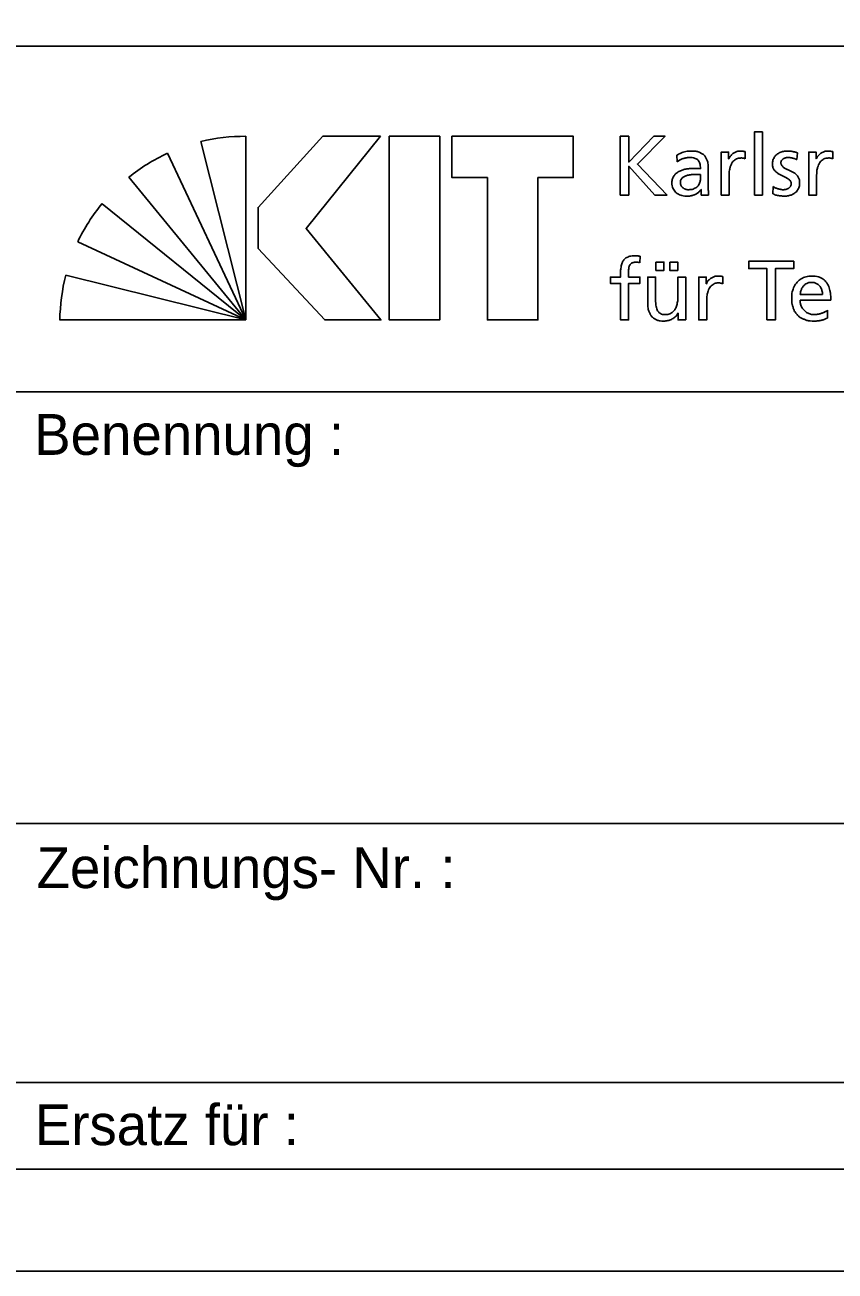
# Model space of a CAD drawing. Extents: x 0 to 148, y 0 to 105.
# Drawn here: x 126.41 to 136.33, y 0 to 15.26 of the extents above; entities that cross this region are included whole.
import ezdxf

# ---------------------------------------------------------------- set-up
doc = ezdxf.new("R2010")
doc.units = 0
doc.layers.add('90_Plankopf', color=7, linetype='Continuous')

msp = doc.modelspace()

# ---------------------------------------------------------------- linework, layer by layer
at = {"layer": '90_Plankopf'}
for p, q in [((102.78, 14.998), (147.25, 14.998)), ((102.78, 14.998), (147.25, 14.998)), ((129.12, 11.647), (129.12, 13.896)), ((133.702, 13.897), (133.702, 13.176)), ((128.569, 13.833), (129.12, 11.647)), ((129.12, 11.647), (128.158, 13.688)), ((134.395, 13.665), (134.4, 13.583)), ((135.232, 13.621), (135.232, 13.708)), ((135.864, 13.61), (135.872, 13.694)), ((136.303, 13.621), (136.303, 13.708)), ((134.78, 13.28), (134.78, 13.497)), ((127.686, 13.396), (129.12, 11.647)), ((134.683, 13.427), (134.683, 13.381)), ((135.574, 13.28), (135.569, 13.193)), ((133.702, 13.176), (133.806, 13.176)), ((134.126, 13.176), (134.277, 13.176)), ((129.12, 11.647), (127.358, 13.071)), ((127.06, 12.603), (129.12, 11.647)), ((133.943, 12.348), (133.947, 12.427)), ((129.12, 11.647), (126.914, 12.197)), ((134.957, 12.091), (134.957, 12.178)), ((136.177, 11.96), (135.904, 11.96)), ((135.904, 11.888), (136.28, 11.888)), ((136.239, 11.668), (136.239, 11.765)), ((126.841, 11.647), (129.12, 11.647)), ((126.25, 10.768), (147.25, 10.768)), ((126.25, 5.48), (147.25, 5.48)), ((126.25, 2.308), (147.25, 2.308)), ((147.25, 1.25), (102.78, 1.25)), ((105.7, 1.25), (147.25, 1.25)), ((105.7, 1.25), (147.25, 1.25))]:
    msp.add_line(p, q, dxfattribs=at)
for points in [[(0, 0), (148.5, 0), (148.5, 105), (0, 105)], [(6.25, 103.75), (147.25, 103.75), (147.25, 1.25), (6.25, 1.25)], [(130.767, 13.897), (130.059, 13.897), (129.268, 13.025), (129.268, 12.523), (130.084, 11.647), (130.771, 11.647), (129.856, 12.766)], [(131.493, 13.897), (131.493, 11.647), (130.875, 11.647), (130.875, 13.897)], [(131.641, 13.897), (131.641, 13.39), (132.075, 13.39), (132.075, 11.647), (132.693, 11.647), (132.693, 13.39), (133.127, 13.39), (133.127, 13.897)]]:
    msp.add_lwpolyline(points, close=True, dxfattribs=at)
for points in [[(134.277, 13.176), (133.912, 13.556), (134.25, 13.897), (134.113, 13.897), (133.806, 13.58), (133.806, 13.897), (133.702, 13.897)], [(135.345, 13.176), (135.442, 13.176), (135.442, 13.95), (135.345, 13.95), (135.345, 13.176)], [(135.03, 13.621), (135.028, 13.621), (135.028, 13.703), (134.938, 13.703), (134.938, 13.176), (135.035, 13.176), (135.035, 13.416)], [(136.102, 13.621), (136.1, 13.621), (136.1, 13.703), (136.009, 13.703), (136.009, 13.176), (136.106, 13.176), (136.106, 13.416)], [(133.806, 13.176), (133.806, 13.529), (134.126, 13.176)], [(134.691, 13.245), (134.693, 13.245), (134.693, 13.176), (134.784, 13.176)], [(135.498, 11.647), (135.601, 11.647), (135.601, 12.276), (135.825, 12.276), (135.825, 12.367), (135.274, 12.367), (135.274, 12.276), (135.498, 12.276), (135.498, 11.647)], [(133.706, 12.221), (133.706, 12.173), (133.582, 12.173), (133.582, 12.094), (133.706, 12.094), (133.706, 11.647), (133.803, 11.647), (133.803, 12.094), (133.942, 12.094), (133.942, 12.173), (133.803, 12.173), (133.803, 12.23)], [(134.139, 12.356), (134.139, 12.253), (134.236, 12.253), (134.236, 12.356), (134.139, 12.356)], [(134.308, 12.356), (134.308, 12.253), (134.405, 12.253), (134.405, 12.356), (134.308, 12.356)], [(134.135, 11.9), (134.135, 12.173), (134.038, 12.173), (134.038, 11.86)], [(134.504, 11.647), (134.504, 12.173), (134.407, 12.173), (134.407, 11.929)], [(134.756, 12.091), (134.754, 12.091), (134.754, 12.173), (134.663, 12.173), (134.663, 11.647), (134.76, 11.647), (134.76, 11.886)], [(134.408, 11.73), (134.41, 11.73), (134.41, 11.647), (134.504, 11.647)]]:
    msp.add_lwpolyline(points, dxfattribs=at)
for centre, start, end in [((129.112, 11.514), 89.8053, 103.1895), ((129.165, 11.529), 115.0126, 128.3968), ((129.204, 11.566), 140.7898, 154.174), ((129.223, 11.609), 165.7222, 179.1064)]:
    msp.add_arc(centre, 2.382, start, end, dxfattribs=at)
for points in [[(134.78, 13.497), (134.78, 13.545), (134.773, 13.585), (134.758, 13.617), (134.744, 13.65), (134.721, 13.674), (134.69, 13.69), (134.659, 13.707), (134.618, 13.715), (134.568, 13.715), (134.535, 13.715), (134.503, 13.71), (134.474, 13.701), (134.445, 13.692), (134.419, 13.68), (134.395, 13.665)], [(134.4, 13.583), (134.413, 13.594), (134.428, 13.604), (134.445, 13.611), (134.461, 13.62), (134.479, 13.626), (134.497, 13.63), (134.516, 13.634), (134.534, 13.637), (134.553, 13.637), (134.585, 13.637), (134.61, 13.631), (134.629, 13.621), (134.649, 13.611), (134.662, 13.596), (134.67, 13.575), (134.679, 13.555), (134.683, 13.53), (134.683, 13.499)], [(135.232, 13.708), (135.225, 13.709), (135.218, 13.71), (135.212, 13.712), (135.206, 13.713), (135.199, 13.713), (135.192, 13.714), (135.185, 13.715), (135.177, 13.715), (135.168, 13.715), (135.149, 13.715), (135.131, 13.711), (135.113, 13.703), (135.095, 13.695), (135.079, 13.684), (135.065, 13.67), (135.051, 13.656), (135.039, 13.639), (135.03, 13.621)], [(135.035, 13.416), (135.035, 13.46), (135.041, 13.498), (135.052, 13.53), (135.064, 13.562), (135.081, 13.587), (135.102, 13.604), (135.124, 13.621), (135.149, 13.63), (135.178, 13.63), (135.186, 13.631), (135.195, 13.63), (135.204, 13.629), (135.214, 13.627), (135.223, 13.625), (135.232, 13.621)], [(135.872, 13.694), (135.854, 13.7), (135.834, 13.705), (135.815, 13.709), (135.795, 13.713), (135.774, 13.715), (135.752, 13.715), (135.726, 13.715), (135.701, 13.712), (135.679, 13.705), (135.656, 13.698), (135.637, 13.688), (135.62, 13.675), (135.603, 13.662), (135.59, 13.645), (135.58, 13.625), (135.571, 13.604), (135.566, 13.58), (135.566, 13.553), (135.566, 13.532), (135.571, 13.514), (135.579, 13.498), (135.587, 13.483), (135.598, 13.47), (135.611, 13.459), (135.625, 13.447), (135.64, 13.437), (135.656, 13.429), (135.672, 13.42), (135.688, 13.412), (135.704, 13.404), (135.721, 13.397), (135.735, 13.389), (135.749, 13.38), (135.762, 13.373), (135.773, 13.363), (135.782, 13.353), (135.79, 13.343), (135.794, 13.331), (135.794, 13.318), (135.794, 13.304), (135.791, 13.292), (135.785, 13.282), (135.779, 13.272), (135.771, 13.265), (135.761, 13.259), (135.751, 13.253), (135.741, 13.249), (135.729, 13.246), (135.718, 13.244), (135.706, 13.242), (135.695, 13.242), (135.685, 13.242), (135.674, 13.244), (135.66, 13.247), (135.646, 13.249), (135.631, 13.253), (135.616, 13.259), (135.601, 13.265), (135.587, 13.271), (135.574, 13.28)], [(135.569, 13.193), (135.592, 13.181), (135.615, 13.174), (135.639, 13.17), (135.664, 13.166), (135.689, 13.164), (135.714, 13.164), (135.737, 13.164), (135.76, 13.167), (135.782, 13.174), (135.804, 13.18), (135.823, 13.191), (135.841, 13.204), (135.858, 13.217), (135.872, 13.234), (135.882, 13.255), (135.892, 13.276), (135.897, 13.3), (135.897, 13.328), (135.897, 13.352), (135.893, 13.372), (135.885, 13.389), (135.876, 13.406), (135.866, 13.42), (135.852, 13.431), (135.839, 13.443), (135.824, 13.453), (135.807, 13.461), (135.791, 13.469), (135.775, 13.477), (135.759, 13.484), (135.743, 13.491), (135.728, 13.499), (135.714, 13.507), (135.701, 13.515), (135.69, 13.524), (135.682, 13.534), (135.674, 13.545), (135.669, 13.557), (135.669, 13.573), (135.669, 13.587), (135.674, 13.599), (135.682, 13.609), (135.691, 13.618), (135.702, 13.625), (135.716, 13.63), (135.73, 13.634), (135.745, 13.637), (135.762, 13.637), (135.768, 13.637), (135.776, 13.636), (135.785, 13.634), (135.794, 13.633), (135.803, 13.631), (135.814, 13.628), (135.824, 13.626), (135.833, 13.623), (135.842, 13.62), (135.851, 13.616), (135.859, 13.613), (135.864, 13.61)], [(136.303, 13.708), (136.296, 13.709), (136.29, 13.71), (136.284, 13.712), (136.277, 13.713), (136.271, 13.713), (136.264, 13.714), (136.257, 13.715), (136.248, 13.715), (136.239, 13.715), (136.22, 13.715), (136.202, 13.711), (136.184, 13.703), (136.167, 13.695), (136.151, 13.684), (136.136, 13.67), (136.122, 13.656), (136.11, 13.639), (136.102, 13.621)], [(136.106, 13.416), (136.106, 13.46), (136.112, 13.498), (136.124, 13.53), (136.136, 13.562), (136.152, 13.587), (136.173, 13.604), (136.195, 13.621), (136.22, 13.63), (136.249, 13.63), (136.258, 13.631), (136.266, 13.63), (136.276, 13.629), (136.285, 13.627), (136.294, 13.625), (136.303, 13.621)], [(134.683, 13.499), (134.67, 13.5), (134.658, 13.501), (134.647, 13.501), (134.636, 13.501), (134.626, 13.501), (134.615, 13.501), (134.604, 13.501), (134.592, 13.501), (134.579, 13.501), (134.559, 13.501), (134.538, 13.5), (134.516, 13.496), (134.493, 13.492), (134.471, 13.487), (134.45, 13.478), (134.429, 13.47), (134.41, 13.46), (134.392, 13.446), (134.375, 13.433), (134.361, 13.416), (134.351, 13.397), (134.34, 13.377), (134.335, 13.354), (134.335, 13.328), (134.335, 13.29), (134.344, 13.259), (134.36, 13.235), (134.376, 13.211), (134.399, 13.193), (134.427, 13.181), (134.456, 13.17), (134.49, 13.164), (134.528, 13.164), (134.55, 13.164), (134.57, 13.167), (134.588, 13.172), (134.605, 13.177), (134.621, 13.184), (134.634, 13.192), (134.648, 13.2), (134.659, 13.209), (134.668, 13.218), (134.678, 13.228), (134.685, 13.236), (134.691, 13.245)], [(134.683, 13.381), (134.683, 13.354), (134.677, 13.331), (134.666, 13.31), (134.655, 13.289), (134.638, 13.273), (134.617, 13.261), (134.595, 13.249), (134.568, 13.243), (134.536, 13.242), (134.525, 13.242), (134.514, 13.244), (134.502, 13.248), (134.491, 13.252), (134.48, 13.257), (134.47, 13.264), (134.461, 13.272), (134.453, 13.281), (134.447, 13.291), (134.441, 13.302), (134.438, 13.314), (134.438, 13.328), (134.438, 13.347), (134.443, 13.362), (134.452, 13.374), (134.461, 13.387), (134.473, 13.396), (134.487, 13.404), (134.502, 13.411), (134.517, 13.417), (134.534, 13.42), (134.55, 13.424), (134.566, 13.426), (134.582, 13.428), (134.597, 13.429), (134.61, 13.429), (134.621, 13.429), (134.631, 13.429), (134.641, 13.429), (134.652, 13.428), (134.662, 13.428), (134.672, 13.427), (134.683, 13.427)], [(134.784, 13.176), (134.783, 13.181), (134.782, 13.188), (134.782, 13.197), (134.781, 13.205), (134.781, 13.216), (134.78, 13.23), (134.78, 13.243), (134.78, 13.26), (134.78, 13.28)], [(133.947, 12.427), (133.938, 12.428), (133.928, 12.43), (133.917, 12.431), (133.906, 12.432), (133.895, 12.433), (133.882, 12.433), (133.847, 12.433), (133.818, 12.428), (133.794, 12.418), (133.771, 12.408), (133.753, 12.394), (133.741, 12.375), (133.728, 12.356), (133.719, 12.334), (133.714, 12.308), (133.708, 12.282), (133.706, 12.253), (133.706, 12.221)], [(133.803, 12.23), (133.803, 12.247), (133.804, 12.264), (133.806, 12.279), (133.808, 12.294), (133.812, 12.307), (133.819, 12.319), (133.825, 12.33), (133.835, 12.339), (133.847, 12.345), (133.86, 12.351), (133.876, 12.354), (133.897, 12.354), (133.905, 12.354), (133.914, 12.354), (133.922, 12.353), (133.93, 12.352), (133.938, 12.35), (133.943, 12.348)], [(134.957, 12.178), (134.95, 12.179), (134.943, 12.181), (134.938, 12.182), (134.931, 12.183), (134.925, 12.184), (134.917, 12.184), (134.911, 12.185), (134.902, 12.185), (134.893, 12.185), (134.874, 12.185), (134.856, 12.181), (134.838, 12.173), (134.821, 12.165), (134.805, 12.154), (134.79, 12.14), (134.776, 12.126), (134.764, 12.11), (134.756, 12.091)], [(134.76, 11.886), (134.76, 11.93), (134.766, 11.968), (134.778, 12), (134.789, 12.032), (134.806, 12.057), (134.827, 12.074), (134.849, 12.092), (134.874, 12.1), (134.903, 12.1), (134.912, 12.101), (134.92, 12.1), (134.93, 12.099), (134.939, 12.097), (134.948, 12.095), (134.957, 12.091)], [(136.28, 11.888), (136.28, 11.931), (136.276, 11.97), (136.268, 12.006), (136.26, 12.042), (136.247, 12.073), (136.229, 12.1), (136.211, 12.127), (136.188, 12.148), (136.158, 12.162), (136.128, 12.177), (136.091, 12.185), (136.047, 12.185), (136.01, 12.185), (135.976, 12.178), (135.946, 12.166), (135.916, 12.152), (135.89, 12.134), (135.868, 12.111), (135.847, 12.087), (135.83, 12.059), (135.819, 12.026), (135.807, 11.994), (135.801, 11.958), (135.801, 11.919), (135.801, 11.876), (135.806, 11.837), (135.817, 11.802), (135.828, 11.767), (135.845, 11.737), (135.867, 11.712), (135.889, 11.687), (135.918, 11.668), (135.952, 11.655), (135.986, 11.641), (136.027, 11.634), (136.073, 11.634), (136.102, 11.634), (136.126, 11.636), (136.147, 11.64), (136.167, 11.644), (136.184, 11.648), (136.199, 11.653), (136.214, 11.659), (136.227, 11.664), (136.239, 11.668)], [(135.904, 11.96), (135.906, 11.977), (135.91, 11.995), (135.916, 12.012), (135.922, 12.029), (135.931, 12.045), (135.942, 12.059), (135.953, 12.073), (135.967, 12.085), (135.984, 12.093), (136.001, 12.102), (136.022, 12.107), (136.045, 12.107), (136.066, 12.107), (136.085, 12.103), (136.101, 12.095), (136.117, 12.088), (136.131, 12.077), (136.142, 12.064), (136.153, 12.05), (136.162, 12.035), (136.168, 12.017), (136.174, 11.999), (136.177, 11.981), (136.177, 11.96)], [(134.407, 11.929), (134.407, 11.897), (134.404, 11.868), (134.397, 11.841), (134.391, 11.815), (134.381, 11.792), (134.368, 11.773), (134.355, 11.754), (134.338, 11.739), (134.318, 11.728), (134.298, 11.718), (134.274, 11.713), (134.247, 11.713), (134.219, 11.714), (134.197, 11.722), (134.18, 11.736), (134.164, 11.75), (134.152, 11.771), (134.145, 11.798), (134.139, 11.825), (134.135, 11.859), (134.135, 11.9)], [(134.038, 11.86), (134.038, 11.813), (134.045, 11.772), (134.059, 11.739), (134.073, 11.705), (134.095, 11.679), (134.124, 11.661), (134.153, 11.644), (134.19, 11.634), (134.236, 11.634), (134.26, 11.634), (134.284, 11.638), (134.306, 11.646), (134.329, 11.653), (134.349, 11.665), (134.367, 11.679), (134.384, 11.693), (134.398, 11.71), (134.408, 11.73)], [(136.239, 11.765), (136.233, 11.76), (136.225, 11.755), (136.213, 11.749), (136.202, 11.743), (136.189, 11.737), (136.174, 11.732), (136.159, 11.726), (136.143, 11.722), (136.126, 11.718), (136.11, 11.715), (136.094, 11.713), (136.077, 11.713), (136.054, 11.713), (136.032, 11.717), (136.012, 11.725), (135.991, 11.734), (135.972, 11.746), (135.956, 11.761), (135.94, 11.777), (135.927, 11.795), (135.918, 11.817), (135.909, 11.838), (135.904, 11.862), (135.904, 11.888)]]:
    msp.add_open_spline(points, degree=3, dxfattribs=at)

# ---------------------------------------------------------------- texts
for s, p in [('Benennung :', (126.528, 9.995)), ('Zeichnungs- Nr. :', (126.557, 4.69)), ('Ersatz für :', (126.535, 1.542))]:
    msp.add_text(s, height=0.5, dxfattribs=at).set_placement(p)

doc.saveas('drawing.dxf')
